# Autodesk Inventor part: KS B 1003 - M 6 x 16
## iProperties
Created: 2009-02
Part Number: KS B 1003 - M 6 x 16
Material: Steel, Mild
Description: 6각머리 태핑 나사
Document SubType Name: Modeling
Standard: KS B 1003
Designer: KYOUNG IL JANG
Standards Organization: KS
Language: ko-KR
Size Designation: M 6 x 16
Categories: <MemberInstance><Categories><Category DisplayName="조임쇠" InternalName="e4da775c-781d-43d5-af7c-5136215cf5a6" Mnemonic="FSTN"><Category DisplayName="볼트" InternalN
Density: 1 g/cm^3
Company: 한국ATC센터
IsCustomPart: 0
Author: KYOUNG IL JANG
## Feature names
1. Fillet2
